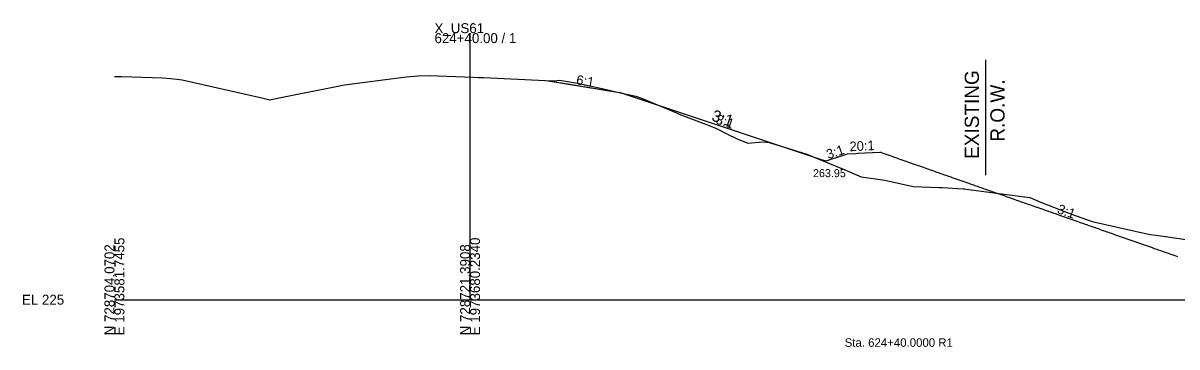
# Model space of a CAD drawing. Extents: x -26 to 630, y -39 to 9098.
# Drawn here: x -25.7 to 298.8, y 986.7 to 1077.8 of the extents above; entities that cross this region are included whole.
import ezdxf

# ---------------------------------------------------------------- set-up
doc = ezdxf.new("R2010")
doc.units = 0
for name, color, linetype in [('CONST_DCH', 7, 'Continuous'), ('Default', 7, 'Continuous'), ('Draft_XS_Grid', 7, 'Continuous'), ('Draft_XS_Text', 7, 'Continuous'), ('DTM CONTOURS_MAJOR', 7, 'Continuous'), ('DTM_X_GROUND', 7, 'Continuous'), ('X_DTM_CONTOURS_MAJOR', 7, 'Continuous'), ('XS_CELL', 7, 'Continuous'), ('XS_P_GROUND', 7, 'Continuous'), ('XS_P_ROW', 7, 'Continuous'), ('XS_P_TX_DCH', 7, 'Continuous'), ('XS_P_TX_FS_BS', 7, 'Continuous'), ('XS_X_ROW', 7, 'Continuous')]:
    doc.layers.add(name, color=color, linetype=linetype)

msp = doc.modelspace()

# ---------------------------------------------------------------- linework, layer by layer
at = {"layer": 'DTM_X_GROUND'}
msp.add_lwpolyline([(0, 1062.83), (2.01, 1062.77), (13.55, 1062.4), (15.84, 1062.22), (17.57, 1062.09), (19.09, 1061.91), (41.41, 1056.83), (43.69, 1056.24), (46.36, 1056.78), (64.67, 1060.48), (81.27, 1062.61), (83.07, 1062.78), (84.41, 1062.91), (85.37, 1062.95), (88.47, 1063.07), (100.85, 1062.62), (102.24, 1062.57), (103.81, 1062.49), (123.08, 1061.57), (123.79, 1061.63), (125.16, 1061.77), (130.21, 1060.89), (137.18, 1059.4), (142.72, 1058.15), (146.63, 1057.24), (148.18, 1056.7), (158.01, 1052.55), (158.78, 1052.18), (166.46, 1049.32), (169.15, 1048.29), (172.19, 1046.68), (175.11, 1045.26), (178.07, 1044.07), (182.34, 1044.4), (184.15, 1044.21), (194.74, 1040.91), (204.72, 1036.84), (209.96, 1034.53), (216.61, 1033.65), (224.59, 1031.89), (231.88, 1031.56), (232.8, 1031.58), (238.69, 1031.24), (239.04, 1031.18), (239.49, 1031.11), (257.41, 1028.73), (260.69, 1027.33), (269.1, 1024.07), (274.98, 1022.01), (290.8, 1018.42), (296.18, 1017.68), (305.07, 1016.38)], dxfattribs=at)
at = {"layer": 'XS_CELL'}
for p, q in [((100, 1000), (100, 1075)), ((0, 1000), (100, 1000)), ((100, 1000), (450, 1000))]:
    msp.add_line(p, q, dxfattribs=at)
at = {"layer": 'XS_P_GROUND'}
for points in [[(122, 1061.62), (142, 1058.28)], [(122, 1061.62), (126.86, 1060.81), (142, 1058.28)], [(122, 1061.62), (142, 1058.28)], [(215.57, 1041.43), (215.55, 1041.43), (215.3, 1041.42), (213.26, 1041.31), (213.13, 1041.31), (211.14, 1041.21), (211.05, 1041.2), (209.17, 1041.11), (209.02, 1041.1), (208.46, 1041.07), (206, 1040.95), (204.06, 1040.3), (203.94, 1040.26), (202.67, 1039.84), (202.32, 1039.72), (200, 1038.95), (198.57, 1039.43), (142, 1058.28)], [(215.57, 1041.43), (215.58, 1041.43), (215.58, 1041.43), (216.68, 1041.04), (216.71, 1041.03), (217.78, 1040.66), (217.83, 1040.64), (218.87, 1040.27), (218.96, 1040.24), (219.97, 1039.88), (220.08, 1039.85), (221.07, 1039.5), (221.2, 1039.45), (222.17, 1039.11), (222.33, 1039.06), (223.26, 1038.73), (224.18, 1038.41), (224.36, 1038.34), (225.28, 1038.02), (225.46, 1037.96), (226.39, 1037.63), (226.56, 1037.57), (227.49, 1037.25), (227.65, 1037.19), (228.59, 1036.86), (228.75, 1036.8), (229.69, 1036.47), (229.85, 1036.42), (230.79, 1036.09), (230.94, 1036.03), (231.89, 1035.7), (232.04, 1035.65), (232.99, 1035.31), (233.14, 1035.26), (234.1, 1034.92), (234.24, 1034.88), (235.2, 1034.54), (235.33, 1034.49), (236.3, 1034.15), (236.43, 1034.1), (237.4, 1033.76), (237.53, 1033.72), (238.5, 1033.38), (238.63, 1033.33), (239.61, 1032.99), (239.72, 1032.95), (240.71, 1032.6), (240.82, 1032.56), (241.81, 1032.21), (241.92, 1032.18), (242.92, 1031.83), (243.02, 1031.79), (244.02, 1031.44), (244.11, 1031.41), (245.12, 1031.05), (245.21, 1031.02), (246.23, 1030.66), (246.31, 1030.64), (247.33, 1030.28), (247.41, 1030.25), (248.44, 1029.89), (248.5, 1029.87), (249.54, 1029.5), (249.6, 1029.48), (250.65, 1029.11), (250.7, 1029.09), (251.75, 1028.72), (251.8, 1028.71), (252.83, 1028.34), (252.89, 1028.32), (253.92, 1027.96), (253.99, 1027.94), (255, 1027.58), (255.09, 1027.55), (256.08, 1027.2), (256.18, 1027.17), (257.17, 1026.82), (257.28, 1026.78), (258.25, 1026.44), (258.38, 1026.4), (259.33, 1026.06), (259.48, 1026.01), (260.44, 1025.68), (260.57, 1025.63), (261.54, 1025.29), (261.67, 1025.24), (262.64, 1024.9), (262.77, 1024.86), (263.74, 1024.52), (263.87, 1024.47), (264.84, 1024.13), (264.96, 1024.09), (265.93, 1023.74), (266.06, 1023.7), (267.03, 1023.36), (267.16, 1023.31), (268.13, 1022.97), (268.26, 1022.93), (269.23, 1022.59), (269.35, 1022.54), (270.33, 1022.2), (270.45, 1022.16), (271.42, 1021.82), (271.55, 1021.77), (272.51, 1021.43), (272.65, 1021.39), (273.61, 1021.05), (273.74, 1021), (274.7, 1020.66), (274.84, 1020.62), (275.8, 1020.28), (275.94, 1020.23), (276.89, 1019.9), (277.03, 1019.85), (277.98, 1019.51), (278.13, 1019.46), (279.06, 1019.13), (279.23, 1019.08), (280.15, 1018.75), (280.33, 1018.69), (281.23, 1018.37), (281.42, 1018.3), (282.31, 1017.99), (282.52, 1017.92), (283.4, 1017.61), (283.62, 1017.53), (284.48, 1017.23), (284.72, 1017.15), (285.56, 1016.85), (285.81, 1016.76), (286.64, 1016.47), (286.91, 1016.38), (287.72, 1016.09), (288.01, 1015.99), (288.8, 1015.71), (289.11, 1015.61), (289.87, 1015.34), (290.2, 1015.22), (290.95, 1014.96), (291.3, 1014.84), (292.02, 1014.58), (292.4, 1014.45), (293.09, 1014.21), (293.5, 1014.07), (294.16, 1013.83), (294.59, 1013.68), (295.23, 1013.46), (295.69, 1013.3), (296.3, 1013.08), (296.79, 1012.91), (297.37, 1012.7), (297.89, 1012.52), (298.44, 1012.33), (298.98, 1012.14)]]:
    msp.add_lwpolyline(points, dxfattribs=at)
at = {"layer": 'XS_X_ROW'}
msp.add_line((245, 1035), (245, 1067.48), dxfattribs=at)

# ---------------------------------------------------------------- texts
at = {"layer": 'CONST_DCH'}
msp.add_text('X', height=0.001, dxfattribs=at).set_placement((215.57, 1041.43))
at = {"layer": 'Default'}
msp.add_text('X', height=0.12, dxfattribs=at).set_placement((249.73, 1029.68))
msp.add_text('X', height=0.12, dxfattribs=at).set_placement((249.73, 1029.68))
at = {"layer": 'Draft_XS_Grid'}
msp.add_text('-', height=0.0001, dxfattribs=at).set_placement((0, 1000))
msp.add_text('-', height=0.0001, dxfattribs=at).set_placement((0, 1000))
at = {"layer": 'Draft_XS_Text'}
msp.add_text('Sta. 624+40.0000 R1', height=2.4, dxfattribs=at).set_placement((205.34, 986.75))
msp.add_text('Sta. 624+40.0000 R1', height=2.4, dxfattribs=at).set_placement((205.34, 986.75))
at = {"layer": 'DTM CONTOURS_MAJOR'}
msp.add_text('X', height=0.001, dxfattribs=at).set_placement((200, 1038.95))
at = {"layer": 'X_DTM_CONTOURS_MAJOR'}
for height, p in [(0.12, (121.96, 1061.56)), (0.12, (121.96, 1061.56)), (0.001, (122, 1061.62)), (0.12, (141.96, 1058.22)), (0.12, (141.96, 1058.22)), (0.001, (142, 1058.28)), (0.12, (219.96, 1041.59)), (0.12, (219.96, 1041.59)), (0.001, (206, 1040.95)), (0.12, (235.05, 1033.5)), (0.12, (235.05, 1033.5))]:
    msp.add_text('X', height=height, dxfattribs=at).set_placement(p)
at = {"layer": 'XS_CELL'}
for s, p in [('X_US61', (90, 1075)), ('624+40.00 / 1', (90, 1072.2)), ('EL 225', (-26, 998.6))]:
    msp.add_text(s, height=2.8, dxfattribs=at).set_placement(p)
for s, p in [('E 1973581.7455', (2.8, 990)), ('E 1973680.2340', (102.8, 990)), ('N 728704.0702', (0, 990)), ('N 728721.3908', (100, 990))]:
    msp.add_text(s, height=2.8, rotation=90, dxfattribs=at).set_placement(p)
at = {"layer": 'XS_P_ROW'}
for s, p in [('EXISTING', (243.1, 1039.62)), ('R.O.W.', (250.3, 1044.46))]:
    msp.add_text(s, height=4, rotation=90, dxfattribs=at).set_placement(p)
at = {"layer": 'XS_P_TX_DCH'}
msp.add_text('263.95', height=2.25, dxfattribs=at).set_placement((196.45, 1034.49))
at = {"layer": 'XS_P_TX_FS_BS'}
for s, height, rotation, p in [('6:1', 2.7, 350.5377, (129.72, 1060.63)), ('3:1', 3.24, 341.5651, (167.69, 1050.49)), ('3:1', 2.7, 341.5651, (168.92, 1049.63)), ('3:1', 2.7, 18.4349, (200.73, 1039.51)), ('20:1', 2.7, 2.8625, (206.79, 1041.76)), ('3:1', 2.7, 340.6507, (264.91, 1024.42))]:
    msp.add_text(s, height=height, rotation=rotation, dxfattribs=at).set_placement(p)

doc.saveas('drawing.dxf')
